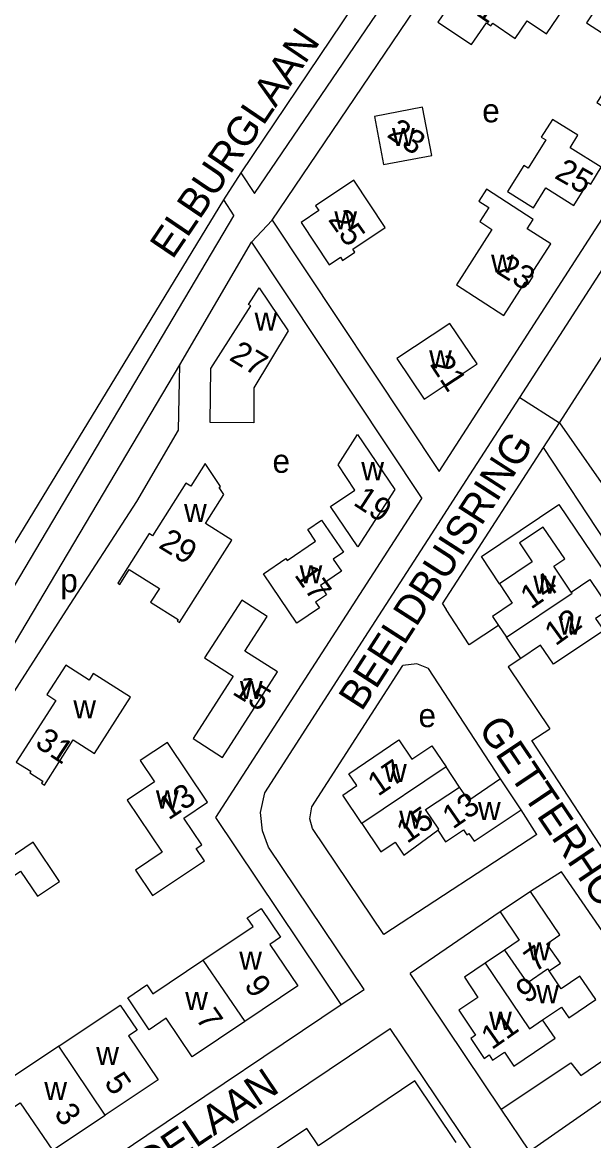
# Model space of a CAD drawing. Extents: x 158356 to 159894, y 383831 to 385260.
# Drawn here: x 158850.2 to 158947.4, y 384584.4 to 384774.6 of the extents above; entities that cross this region are included whole.
import ezdxf

# ---------------------------------------------------------------- set-up
doc = ezdxf.new("R2010")
doc.units = 0
for name, color, linetype in [('BLT_Basislijn', 7, 'Continuous'), ('BLT_Bebouwing', 7, 'Continuous'), ('BLT_Centroide', 7, 'Continuous'), ('BLT_Huisnummer', 7, 'Continuous'), ('BLT_Huisnummer_zonder_bebouwing', 7, 'Continuous'), ('BLT_Onderverdeling_panden', 7, 'Continuous'), ('BLT_Plantopo', 7, 'Continuous'), ('BLT_Straatnaam', 7, 'Continuous'), ('BLT_Vlakafsluiter', 7, 'Continuous')]:
    doc.layers.add(name, color=color, linetype=linetype)

msp = doc.modelspace()

# ---------------------------------------------------------------- linework, layer by layer
at = {"layer": 'BLT_Basislijn'}
for p, q in [((158892.72, 384740.96), (158981.6, 384872.33)), ((158889.73, 384745.46), (158969.38, 384862.96)), ((158887.39, 384748.99), (158884.44, 384744.38)), ((158887.39, 384748.99), (158889.73, 384745.46)), ((158884.44, 384744.38), (158886.22, 384741.7)), ((158805.55, 384605.67), (158886.22, 384741.7)), ((158892.72, 384740.96), (158921.14, 384698.19)), ((158876.99, 384716.34), (158889.21, 384737.2)), ((158889.21, 384737.2), (158918.18, 384693.6)), ((158837.9, 384650.42), (158876.99, 384716.34)), ((158876.77, 384705.19), (158876.99, 384716.34)), ((158923.96, 384693.94), (158934.83, 384710.79)), ((158938.87, 384702.29), (158941.55, 384706.45)), ((158941.55, 384706.45), (158951.13, 384692.76)), ((158869.68, 384693.07), (158876.77, 384705.19)), ((158935.35, 384696.83), (158938.87, 384702.29)), ((158927.79, 384685.12), (158935.35, 384696.83)), ((158857.74, 384674.59), (158869.68, 384693.07)), ((158921, 384689.35), (158923.96, 384693.94)), ((158909.1, 384670.89), (158921, 384689.35)), ((158921.69, 384675.66), (158927.79, 384685.12)), ((158921.69, 384675.66), (158922.28, 384674.72)), ((158842.61, 384651.06), (158857.74, 384674.59)), ((158891.45, 384643.52), (158909.1, 384670.89)), ((158899.44, 384641.14), (158914.95, 384665.2)), ((158937.74, 384636.46), (158935.05, 384640.65)), ((158937.74, 384636.46), (158911.7, 384619.43)), ((158941.9, 384630.1), (158936.65, 384626.75)), ((158948.96, 384619.87), (158941.9, 384630.1)), ((158931.46, 384623.25), (158916.16, 384612.79)), ((158931.67, 384589.7), (158916.16, 384612.79)), ((158904.47, 384607.49), (158908.34, 384610.09)), ((158871.39, 384585.27), (158904.47, 384607.49)), ((158847.11, 384559.33), (158912.8, 384603.45)), ((158936.45, 384582.58), (158931.67, 384589.7)), ((158864.75, 384580.81), (158871.39, 384585.27))]:
    msp.add_line(p, q, dxfattribs=at)
for points in [[(158959.93, 384856.85), (158887.39, 384748.99)], [(158921.14, 384698.19), (158980.6, 384790.41), (158982.62, 384792.82), (158989.15, 384797.43), (159018.93, 384817.4), (159012.95, 384826.2)], [(158934.83, 384710.79), (158986.23, 384790.56), (159020.01, 384812.41)], [(158884.44, 384744.38), (158831.35, 384657.27), (158811.36, 384625.07), (158801.89, 384608.28)], [(158941.55, 384706.45), (158953.64, 384725.22)], [(158987.07, 384664.99), (158970.67, 384653.94), (158938.87, 384702.29)], [(158904.47, 384607.49), (158883.16, 384639.3), (158918.18, 384693.6)], [(158931.35, 384679.05), (158928.31, 384683.75), (158941.46, 384692.58), (158970.04, 384650.29), (158986.56, 384661.35), (159005.35, 384633.8), (158991.18, 384624.3), (158987.84, 384629.27)], [(158931.21, 384672), (158926.23, 384668.68), (158922.28, 384674.72)], [(158934.99, 384666.37), (158932.85, 384664.93), (158939.93, 384654.42)], [(158931.57, 384645.89), (158919.29, 384664.68), (158917.31, 384665.48), (158914.95, 384665.2)], [(158951.18, 384630.53), (158936.87, 384652.41), (158939.93, 384654.42)], [(158908.34, 384610.09), (158892.11, 384634.25), (158891.07, 384637.04), (158890.73, 384640.18), (158891.45, 384643.52)], [(158911.7, 384619.43), (158899.59, 384637.45), (158899.12, 384639.11), (158899.44, 384641.14)], [(158936.45, 384582.58), (158952.55, 384593.8), (158955.38, 384589.59), (158973.61, 384601.84), (158975.82, 384598.55), (158988.93, 384607.24)], [(158931.67, 384589.7), (158943.52, 384597.61), (158945.18, 384595.44), (158953.94, 384601.41), (158955.19, 384599.65), (158962.79, 384604.68), (158963.77, 384603.26), (158967.47, 384605.62)], [(158930.29, 384577.4), (158912.8, 384603.45)]]:
    msp.add_lwpolyline(points, dxfattribs=at)
at = {"layer": 'BLT_Bebouwing'}
for p, q in [((158931.21, 384672), (158932.56, 384669.99)), ((158934.99, 384666.37), (158932.56, 384669.99)), ((158924.58, 384644.51), (158922.28, 384647.92)), ((158935.05, 384640.65), (158931.57, 384645.89)), ((158936.65, 384626.75), (158931.46, 384623.25)), ((158932.24, 384616.75), (158928.96, 384614.54))]:
    msp.add_line(p, q, dxfattribs=at)
for points in [[(158927.51, 384784.36), (158920.86, 384774.63), (158926.64, 384770.81), (158929.15, 384774.49), (158929.9, 384773.97), (158930.23, 384774.45), (158934.02, 384771.86), (158936.06, 384774.85), (158939.35, 384772.61), (158943.25, 384778.32), (158937.72, 384782.1), (158935.52, 384778.89)], [(158949.27, 384779.28), (158946.17, 384774.48), (158954.14, 384769.33), (158951.16, 384764.68), (158950.57, 384765.04), (158947.91, 384760.98), (158952.83, 384757.8), (158955.93, 384762.58), (158956.93, 384761.93), (158959.46, 384765.87), (158962.14, 384770.01), (158956.92, 384773.38), (158957.19, 384773.8), (158952.66, 384776.73), (158952.83, 384776.98)], [(158906.59, 384747.73), (158900.1, 384743.36), (158900.65, 384742.56), (158897.63, 384740.52), (158902.42, 384733.36), (158904.33, 384734.63), (158904.7, 384734.1), (158906.78, 384735.47), (158906.42, 384736.01), (158911.94, 384739.71)], [(158929.55, 384743.08), (158928.01, 384740.7), (158930.08, 384739.36), (158924.05, 384729.91), (158932.09, 384724.73), (158935.74, 384730.38), (158936.26, 384730.05), (158937.12, 384731.4), (158936.72, 384731.66), (158940.11, 384736.9), (158936.1, 384739.49), (158937.12, 384741.07), (158929.19, 384746.21), (158927.87, 384744.17)], [(158890.52, 384729.42), (158895.44, 384722.09), (158889.6, 384712.42), (158889.57, 384706.46), (158882.16, 384706.51), (158882.28, 384715.69), (158889.11, 384726.34), (158888.71, 384726.6)], [(158922.93, 384723.37), (158913.92, 384717.38), (158918.54, 384710.47), (158927.55, 384716.48)], [(158907.23, 384704.49), (158913.55, 384695.13), (158907.26, 384685.37), (158902.63, 384692.23), (158906.8, 384695.03), (158903.92, 384699.33)], [(158866.79, 384678.95), (158868.42, 384681.53), (158873.53, 384678.28), (158872.05, 384675.96), (158876.73, 384673), (158876.57, 384672.74), (158876.94, 384672.5), (158885.84, 384686.51), (158881.39, 384689.33), (158884.52, 384694.26), (158883.71, 384695.47), (158883.91, 384695.61), (158881.3, 384699.53), (158878.9, 384695.66), (158878.04, 384696.21), (158872.34, 384687.26), (158871.79, 384687.61), (158866.45, 384679.17)], [(158887.55, 384676.3), (158881.2, 384666.51), (158886.08, 384663.37), (158879.28, 384652.75), (158884.29, 384649.54), (158893.6, 384664.1), (158888.08, 384667.63), (158891.86, 384673.54)], [(158857.64, 384665.22), (158854.42, 384660.22), (158855.92, 384659.25), (158849.2, 384648.76), (158851.66, 384647.2), (158851.49, 384646.93), (158853.72, 384645.52), (158853.5, 384645.17), (158854.01, 384644.84), (158858.88, 384652.51), (158862.52, 384650.2), (158868.61, 384659.79), (158862.28, 384663.8), (158861.59, 384662.71)], [(158872.39, 384626.04), (158881.2, 384631.96), (158879.8, 384634.04), (158880.73, 384634.65), (158877.69, 384639.19), (158881.74, 384641.92), (158874.9, 384652.09), (158870.26, 384649.01), (158872.69, 384645.38), (158868.04, 384642.25), (158873.99, 384633.4), (158869.48, 384630.37)], [(158856.53, 384628.44), (158852.06, 384635.1), (158847.66, 384632.14), (158847.1, 384632.97), (158847.84, 384633.47), (158845.97, 384636.26), (158845.22, 384635.8), (158842.82, 384639.36), (158836.18, 384634.87), (158842.59, 384625.32), (158849.9, 384630.22), (158852.79, 384625.92)]]:
    msp.add_lwpolyline(points, close=True, dxfattribs=at)
for points in [[(158919.84, 384751.95), (158918.29, 384760.15), (158910.09, 384758.59), (158911.64, 384750.39), (158919.84, 384751.95)], [(158891.24, 384680.76), (158895.04, 384683.36), (158895.27, 384683.02), (158900.11, 384686.33), (158898.76, 384688.3), (158901.11, 384689.9), (158904.82, 384684.47), (158903.09, 384683.29), (158904.49, 384681.23), (158900.92, 384678.79), (158901.98, 384677.23), (158900.09, 384675.95), (158900.75, 384674.99), (158896.93, 384672.39), (158891.24, 384680.76)], [(158943.59, 384677.68), (158940.63, 384682.08), (158942.46, 384683.3), (158938.82, 384688.73), (158934.8, 384686.02), (158936.95, 384682.82), (158931.35, 384679.05)], [(158943.59, 384677.68), (158946.74, 384679.79), (158950.12, 384674.78), (158947.72, 384673.17), (158949.1, 384671.14), (158940.56, 384665.38), (158938.37, 384668.64), (158934.99, 384666.37)], [(158931.35, 384679.05), (158933.54, 384675.79), (158930.19, 384673.52), (158931.21, 384672)], [(158907.98, 384638.3), (158904.74, 384643.11), (158907.13, 384644.74), (158905.76, 384646.76), (158914.28, 384652.51), (158916.47, 384649.23), (158919.85, 384651.52), (158922.28, 384647.92)], [(158931.57, 384645.89), (158926.14, 384642.19), (158924.58, 384644.51)], [(158920.87, 384637.19), (158922.2, 384635.2), (158925.24, 384637.24), (158925.83, 384636.37), (158926.17, 384636.6), (158927.06, 384635.27), (158935.05, 384640.65)], [(158907.98, 384638.3), (158911.21, 384633.5), (158913.62, 384635.12), (158915.09, 384632.93), (158920.87, 384637.19)], [(158939.81, 384613.24), (158941.72, 384614.52), (158939.45, 384617.85), (158941.66, 384619.36), (158936.65, 384626.75)], [(158880.94, 384615.07), (158889.47, 384620.79), (158888.49, 384622.27), (158890.86, 384623.87), (158894.16, 384618.97), (158892.32, 384617.73), (158897.07, 384610.66), (158888.09, 384604.63)], [(158931.46, 384623.25), (158934.71, 384618.43), (158932.24, 384616.75)], [(158888.09, 384604.63), (158879.11, 384598.6), (158874.69, 384605.16), (158871.79, 384603.21), (158868.16, 384608.63), (158871.42, 384610.83), (158872.41, 384609.35), (158880.94, 384615.07)], [(158928.96, 384614.54), (158925.42, 384612.14), (158927.71, 384608.72), (158924.46, 384606.53), (158927.31, 384602.3), (158926.49, 384601.75), (158928.79, 384598.33), (158929.59, 384598.93), (158930.18, 384598.05), (158932.21, 384599.42), (158933.82, 384597.03), (158940.85, 384601.77), (158938.7, 384604.89)], [(158938.7, 384604.89), (158941.9, 384607.06), (158943.14, 384605.24), (158947.76, 384608.37), (158945.06, 384612.36), (158941.86, 384610.18), (158939.81, 384613.24)], [(158856.44, 384600.42), (158866.89, 384607.42), (158869.76, 384603.17), (158868.29, 384602.2), (158873.34, 384594.71), (158864.34, 384588.67)], [(158856.44, 384600.42), (158845.93, 384593.44), (158848.39, 384589.81), (158849.87, 384590.81), (158855.35, 384582.72), (158864.34, 384588.67)], [(158924, 384584.05), (158916.97, 384594.54), (158900.6, 384583.49), (158898.63, 384586.44), (158858.52, 384559.55), (158857.84, 384560.12), (158856.96, 384560.46), (158856.07, 384560.27), (158855.35, 384559.78), (158854.9, 384559.06), (158854.76, 384558.22), (158855.09, 384557.32), (158856.24, 384555.55), (158856.8, 384555.44), (158858.09, 384556.3), (158865.69, 384544.88)]]:
    msp.add_lwpolyline(points, dxfattribs=at)
at = {"layer": 'BLT_Onderverdeling_panden'}
for p, q in [((158922.28, 384647.92), (158907.98, 384638.3)), ((158880.94, 384615.07), (158888.09, 384604.63)), ((158864.34, 384588.67), (158856.44, 384600.42))]:
    msp.add_line(p, q, dxfattribs=at)
for points in [[(158932.56, 384669.99), (158943.73, 384677.48), (158943.59, 384677.68)], [(158920.87, 384637.19), (158921.04, 384637.32), (158918.8, 384640.67), (158924.58, 384644.51)], [(158932.24, 384616.75), (158936.09, 384611.18), (158939.56, 384613.58), (158939.81, 384613.24)], [(158928.96, 384614.54), (158936.47, 384603.38), (158938.7, 384604.89)]]:
    msp.add_lwpolyline(points, dxfattribs=at)
at = {"layer": 'BLT_Plantopo'}
msp.add_lwpolyline([(158940.36, 384758.09), (158938.48, 384755.07), (158939.23, 384754.6), (158936.23, 384749.8), (158935.49, 384750.26), (158932.72, 384745.82), (158937.16, 384743.05), (158939.27, 384746.43), (158944.03, 384743.46), (158946.45, 384747.34), (158946.89, 384747.08), (158948.66, 384749.93), (158943.37, 384753.22), (158944.71, 384755.37)], close=True, dxfattribs=at)
at = {"layer": 'BLT_Vlakafsluiter'}
for p, q in [((158889.21, 384737.2), (158892.72, 384740.96)), ((158934.83, 384710.79), (158941.55, 384706.45))]:
    msp.add_line(p, q, dxfattribs=at)

# ---------------------------------------------------------------- texts
at = {"layer": 'BLT_Centroide'}
for s, p in [('e', (158928.44, 384757.58)), ('w', (158913.09, 384753.55)), ('w', (158903.29, 384739.38)), ('w', (158929.94, 384732.01)), ('w', (158889.72, 384722.15)), ('w', (158919.41, 384715.74)), ('e', (158892.77, 384697.96)), ('w', (158907.87, 384696.7)), ('w', (158877.73, 384689.57)), ('w', (158897.38, 384679.16)), ('p', (158856.69, 384677.64)), ('w', (158937.11, 384677.4)), ('w', (158941.41, 384670.45)), ('w', (158887.23, 384659.49)), ('w', (158858.9, 384656.21)), ('e', (158917.6, 384654.69)), ('w', (158911.75, 384645.38)), ('w', (158872.95, 384640.85)), ('w', (158927.71, 384638.89)), ('w', (158914.33, 384637.44)), ('w', (158936.21, 384615.03)), ('w', (158887.12, 384613.44)), ('w', (158877.93, 384606.58)), ('w', (158937.63, 384607.73)), ('w', (158929.61, 384603.2)), ('w', (158862.8, 384597.2)), ('w', (158853.97, 384591.25))]:
    msp.add_text(s, height=4, dxfattribs=at).set_placement(p)
at = {"layer": 'BLT_Huisnummer'}
for s, rotation, p in [('21', 326.218, (158924.72, 384777.61)), ('23', 325.6669, (158912.05, 384755.22)), ('25', 305.218, (158902.13, 384741.02)), ('23', 328.218, (158930.7, 384731.99)), ('27', 328.6669, (158885.23, 384717.25)), ('21', 303.218, (158919.44, 384716.42)), ('19', 326.6669, (158906.33, 384692.61)), ('29', 328.6669, (158873.22, 384685.32)), ('17', 305.218, (158896.38, 384680.57)), ('14', 34.8722, (158936.73, 384674.64)), ('12', 35.8795, (158940.9, 384668.41)), ('15', 328.3486, (158885.77, 384660.39)), ('31', 326.6669, (158852.19, 384651.53)), ('17', 34.2505, (158910.71, 384642.82)), ('13', 33.3486, (158875.09, 384638.79)), ('13', 34.5668, (158923.44, 384637.24)), ('15', 34.9928, (158915.66, 384634.79)), ('7', 35.7615, (158937.41, 384612.89)), ('9', 304.8063, (158887.84, 384610.78)), ('9', 34.6344, (158935.96, 384607.56)), ('7', 304.8063, (158879.6, 384605.12)), ('11', 35.0807, (158930.07, 384599.72)), ('5', 304.8063, (158864.03, 384594.23)), ('3', 304.8063, (158855.51, 384588.99))]:
    msp.add_text(s, height=4, rotation=rotation, dxfattribs=at).set_placement(p)
at = {"layer": 'BLT_Huisnummer_zonder_bebouwing'}
msp.add_text('25', height=4, rotation=330.218, dxfattribs=at).set_placement((158940.55, 384748.19))
at = {"layer": 'BLT_Straatnaam'}
for s, rotation, p in [('ELBURGLAAN', 55.8477, (158875.76, 384734.12)), ('BEELDBUISRING', 57.1873, (158907.93, 384657.23)), ('GETTERHOF', 303.8882, (158927.64, 384654.46)), ('KATHODELAAN', 33.8882, (158852.88, 384565.01))]:
    msp.add_text(s, height=5, rotation=rotation, dxfattribs=at).set_placement(p)

doc.saveas('drawing.dxf')
